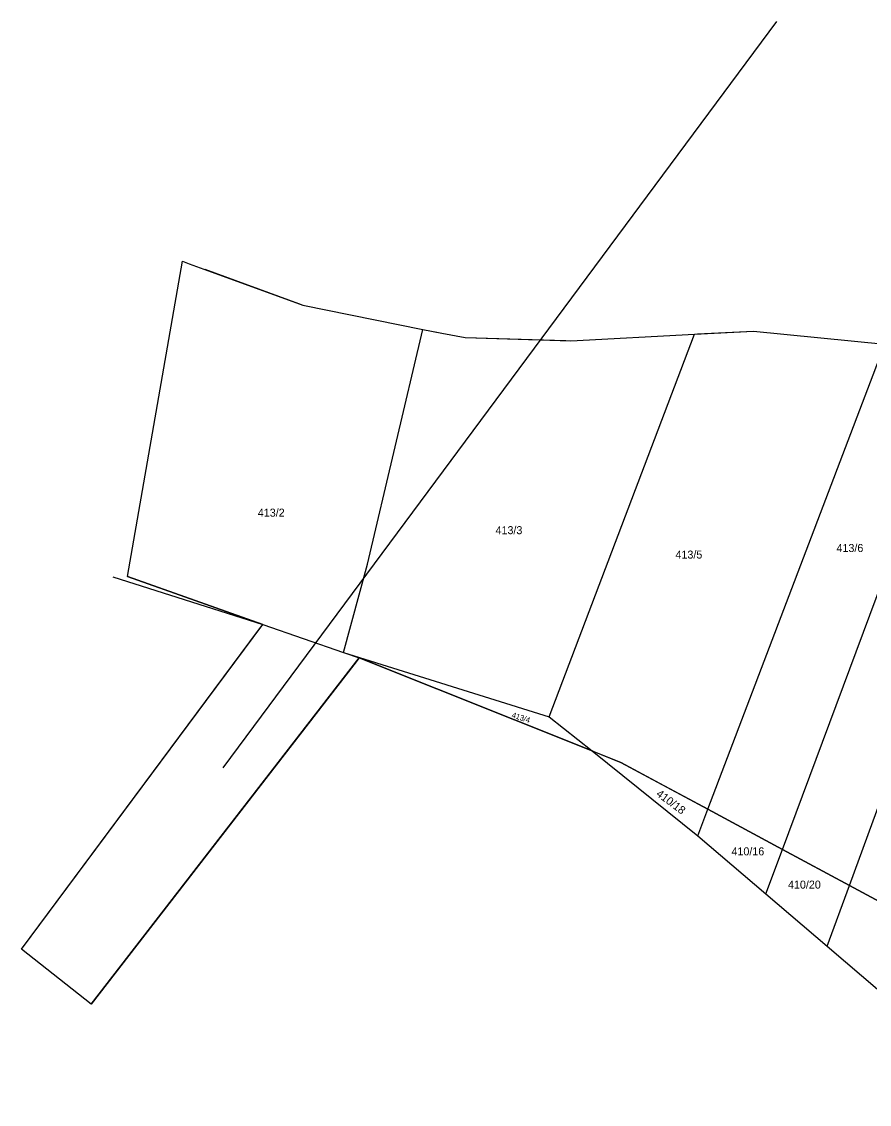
# Model space of a CAD drawing. Extents: x -743888 to -742027, y -1128394 to -1126768.
# Drawn here: x -743813.5 to -743633.6, y -1127020.7 to -1126790.8 of the extents above; entities that cross this region are included whole.
import ezdxf

# ---------------------------------------------------------------- set-up
doc = ezdxf.new("R2010")
doc.units = 0
for name, color, linetype in [('Vrstva 1', 7, 'Continuous'), ('Vrstva 12', 7, 'Continuous'), ('Vrstva 13', 7, 'Continuous'), ('Vrstva 18', 7, 'Continuous'), ('Vrstva 52', 7, 'Continuous'), ('Vrstva 6', 7, 'Continuous')]:
    doc.layers.add(name, color=color, linetype=linetype)

msp = doc.modelspace()

# ---------------------------------------------------------------- linework, layer by layer
at = {"layer": 'Vrstva 1'}
for points in [[(-743791.08, -1126908.6), (-743762.33, -1126918.74)], [(-743813.51, -1126987.67), (-743762.33, -1126918.74)], [(-743762.33, -1126918.74), (-743745.19, -1126924.71)], [(-743798.75, -1126999.39), (-743741.88, -1126925.86)], [(-743745.19, -1126924.71), (-743741.88, -1126925.86)], [(-743741.88, -1126925.86), (-743692.45, -1126945.62)], [(-743692.45, -1126945.62), (-743686.33, -1126948.07)], [(-743686.33, -1126948.07), (-743667.9, -1126958)], [(-743667.9, -1126958), (-743652.05, -1126966.54)], [(-743652.05, -1126966.54), (-743637.84, -1126974.2)], [(-743637.84, -1126974.2), (-743613.12, -1126987.52)]]:
    msp.add_lwpolyline(points, dxfattribs=at)
at = {"layer": 'Vrstva 12'}
msp.add_lwpolyline([(-743653.34, -1126790.75), (-743770.82, -1126949.19)], dxfattribs=at)
at = {"layer": 'Vrstva 13'}
for points in [[(-743774.65, -1126843.34), (-743754.79, -1126850.58)], [(-743754.79, -1126850.58), (-743753.84, -1126850.92)], [(-743753.84, -1126850.92), (-743728.36, -1126856.1)], [(-743728.36, -1126856.1), (-743725.02, -1126856.78)], [(-743725.02, -1126856.78), (-743724.34, -1126856.92)], [(-743724.34, -1126856.92), (-743719.42, -1126857.82)], [(-743696.98, -1126858.5), (-743670.72, -1126857.13)], [(-743670.72, -1126857.13), (-743670.09, -1126857.07)], [(-743670.09, -1126857.07), (-743658.2, -1126856.48)], [(-743658.2, -1126856.48), (-743630.32, -1126859.26)], [(-743719.42, -1126857.82), (-743698.04, -1126858.47)], [(-743698.04, -1126858.47), (-743696.98, -1126858.5)]]:
    msp.add_lwpolyline(points, dxfattribs=at)
at = {"layer": 'Vrstva 52'}
for points in [[(-743555.91, -1127020.65), (-743554.98, -1127018.86), (-743556.57, -1127018), (-743573.98, -1127008.62), (-743588.59, -1127000.75), (-743601.38, -1126993.85), (-743613.12, -1126987.52), (-743637.84, -1126974.2), (-743652.05, -1126966.54), (-743667.9, -1126958), (-743678.11, -1126952.5), (-743686.33, -1126948.07), (-743692.02, -1126945.79), (-743692.45, -1126945.62), (-743741.88, -1126925.86), (-743742.99, -1126927.29), (-743798.75, -1126999.39), (-743813.51, -1126987.67), (-743763.23, -1126919.95), (-743762.33, -1126918.74), (-743791.08, -1126908.6), (-743783.35, -1126864.33), (-743779.39, -1126841.61)], [(-743779.39, -1126841.61), (-743777.93, -1126842.14), (-743753.84, -1126850.92), (-743728.36, -1126856.1), (-743724.34, -1126856.92), (-743719.42, -1126857.82), (-743696.98, -1126858.5), (-743670.72, -1126857.13), (-743658.2, -1126856.48), (-743630.32, -1126859.26)]]:
    msp.add_lwpolyline(points, dxfattribs=at)
at = {"layer": 'Vrstva 6'}
for points in [[(-743740.13, -1126905.97), (-743728.36, -1126856.1)], [(-743701.53, -1126938.34), (-743670.72, -1126857.13)], [(-743667.9, -1126958), (-743630.32, -1126859.26)], [(-743652.05, -1126966.54), (-743613.43, -1126862.82)], [(-743637.84, -1126974.2), (-743598.46, -1126866.7)], [(-743745.19, -1126924.71), (-743740.13, -1126905.97)], [(-743794.19, -1126908.65), (-743762.33, -1126918.74)], [(-743745.19, -1126924.71), (-743701.53, -1126938.34)], [(-743701.53, -1126938.34), (-743692.45, -1126945.62)], [(-743692.45, -1126945.62), (-743670.03, -1126963.61)], [(-743670.03, -1126963.61), (-743667.9, -1126958)], [(-743670.03, -1126963.61), (-743655.57, -1126975.98)], [(-743655.57, -1126975.98), (-743652.05, -1126966.54)], [(-743642.55, -1126987.04), (-743637.84, -1126974.2)], [(-743655.57, -1126975.98), (-743642.55, -1126987.04)], [(-743642.55, -1126987.04), (-743620.19, -1127006.18)]]:
    msp.add_lwpolyline(points, dxfattribs=at)

# ---------------------------------------------------------------- texts
at = {"layer": 'Vrstva 18'}
for s, p in [('413/2', (-743763.39, -1126895.86)), ('413/3', (-743712.94, -1126899.58)), ('413/5', (-743674.75, -1126904.76)), ('413/6', (-743640.58, -1126903.36)), ('410/16', (-743662.87, -1126967.78)), ('410/20', (-743650.87, -1126974.84))]:
    msp.add_text(s, height=1.7, dxfattribs=at).set_placement(p)
for s, height, rotation, p in [('413/4', 1.19, 342.1981, (-743709.61, -1126938.47)), ('410/18', 1.7, 323.2412, (-743679, -1126955.02))]:
    msp.add_text(s, height=height, rotation=rotation, dxfattribs=at).set_placement(p)

doc.saveas('drawing.dxf')
